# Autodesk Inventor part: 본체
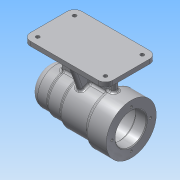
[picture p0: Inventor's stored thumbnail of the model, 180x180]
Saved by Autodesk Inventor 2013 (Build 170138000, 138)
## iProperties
Created: 2016-06
Part Number: 본체
Material: 알루미늄 6061
Document SubType Name: Modeling
Designer: Administrator
Density: 2.71 g/cm^3
Mass: 673.897 g
Surface Area: 647.23 cm^2
Volume: 248.671 cm^3
Author: Administrator
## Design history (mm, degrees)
sketch "스케치1"
  geometry: L1 (0, 0)-(0, 25); L2 (0, 25)-(25, 25); L3 (25, 25)-(25, 27); L4 (25, 27)-(45, 27); L5 (45, 27)-(45, 30); L6 (45, 30)-(84, 30); L7 (84, 30)-(84, 34); L8 (84, 34)-(112, 34); L9 (112, 34)-(112, 0); L10 (0, 0)-(112, 0)
  constraints: 20 end point, 6 perpendicular, 3 parallel, 1 vertical
  dimensions: "d0" = 25 distance of L1.start L1.end; "d1" = 25 distance of L1.end L2.end; "d2" = 2 distance of L2.end L3.end; "d3" = 20 distance of L3.end L4.end; "d4" = 3 distance of L4.end L5.end; "d5" = 39 distance of L5.end L6.end; "d6" = 4 distance of L6.end L7.end; "d7" = 28 distance of L7.end L8.end
revolve "회전1" sketch "스케치1" stored, may be unused: angle "d8" = 90 deg
sketch "스케치2"
  geometry: C1 r 34 at (0, 0) reference; C2 r 21 at (0, 0)
  constraints: 1 centre point, 1 coincident
  dimensions: "d9" = 42 diameter of C2
extrude "돌출1" cut sketch "스케치2" distance "d10" = 15; taper "d11" = 0 deg
sketch "스케치3"
  geometry: C1 r 21 at (0, 0) reference; C2 r 24 at (0, 0)
  constraints: 1 centre point, 1 coincident
  dimensions: "d12" = 48 diameter of C2
extrude "돌출2" cut sketch "스케치3" distance "d13" = 54; taper "d14" = 0 deg
sketch "스케치4"
  geometry: C1 r 24 at (0, 0) reference; C2 r 21 at (0, 0)
  constraints: 1 centre point, 1 coincident
  dimensions: "d15" = 42 diameter of C2
extrude "돌출3" cut sketch "스케치4" distance "d16" = 12; taper "d17" = 0 deg
sketch "스케치5"
  geometry: C1 r 21 at (0, 0) reference; C2 r 17.5 at (0, 0)
  constraints: 1 centre point, 1 coincident
  dimensions: "d18" = 35 diameter of C2
extrude "돌출4" cut sketch "스케치5" distance "d19" = 18; taper "d20" = 0 deg
sketch "스케치6"
  geometry: C1 r 17.5 at (0, 0) reference; C2 r 16 at (0, 0)
  constraints: 1 centre point, 1 coincident
  dimensions: "d21" = 32 diameter of C2
extrude "돌출5" cut sketch "스케치6" distance "d22" = 4; taper "d23" = 0 deg
sketch "스케치7"
  geometry: C1 r 16 at (0, 0) reference; C2 r 10.5 at (0, 0)
  constraints: 1 centre point, 1 coincident
  dimensions: "d24" = 21 diameter of C2
extrude "돌출6" cut sketch "스케치7" distance "d25" = 3; taper "d26" = 0 deg
fillet "모깎기1" dims "d27" = 3
sketch "스케치8"
  geometry: 1 further point
fillet "모깎기2" dims "d28" = 3
sketch "스케치9"
  geometry: 1 further point
fillet "모깎기3" dims "d29" = 0.3
sketch "스케치10"
  geometry: 1 further point
sketch "스케치11" dims "d30" = 52
  geometry: L1 (0, 0)-(0, 26); C1 r 34 at (0, 0) reference; 1 further point
  constraints: 2 coincident, 2 end point, 1 vertical, 1 vertical alignment, 2 other
hole "구멍1" sketch "스케치11" at (0, 26) diameter "d31" = 3.242; stored, may be unused: countersink angle "d35" = 90 deg, drill point angle "d37" = 118 deg; dims "d32" = 8, "d33" = 4, "d34" = 2, "d36" = 11
chamfer "모따기1" distance "d41" = 1; stored, may be unused: second distance "d42" = 2, angle "d43" = 45 deg
fillet "모깎기4" dims "d44" = 10
fillet "모깎기5" dims "d45" = 3
node "작업 평면1"
sketch "스케치12"
  geometry: L1 (0, 15)-(0, -15) reference; L2 (-112, 34)-(-112, -34) reference; L3 (0, 0)-(0, 35); L4 (0, 35)-(-112, 35); L5 (-112, 35)-(-112, -35); L6 (-112, -35)-(0, -35); L7 (0, -35)-(0, 0)
  constraints: 10 end point, 2 parallel, 2 perpendicular, 1 point on line
  dimensions: "d47" = 35 distance of L3.start L3.end; "d48" = 112 distance of L3.end L4.end; "d49" = 70 distance of L4.end L5.end
extrude "돌출7" join sketch "스케치12" distance "d50" = 10; taper "d51" = 0 deg
sketch "스케치13"
  geometry: L1 (0, 35)-(-112, 35) reference; L2 (-112, -35)-(0, -35) reference; L3 (-56, -35)-(-56, 35); L4 (-20, 4)-(-92, 4); L5 (-92, 4)-(-92, -4); L6 (-92, -4)-(-20, -4); L7 (-20, -4)-(-20, 4); L8 (-20, 4)-(-92, -4); L9 (-92, 4)-(-20, -4); 2 further points
  constraints: 14 end point, 5 midpoint, 2 parallel, 1 horizontal, 1 perpendicular
  dimensions: "d54" = 8 distance of L5.end L4.end; "d56" = 6.34019 deg angle of L1 L8
extrude "돌출8" join sketch "스케치13" stored distance "d57" = 10; taper "d58" = 0 deg
node "작업 평면2"
sketch "스케치14"
  geometry: L1 (-35, 70)-(-35, 60) reference; L2 (35, 60)-(-35, 60) reference; L3 (-35, 60)-(-28, 60); L4 (-28, 60)-(-16.9, 29.502); 2 further points
  constraints: 4 end point, 1 point on line, 2 other
  dimensions: "d60" = 7 distance of L1.end L3.end; "d61" = 110 deg angle of L3 L4
feature "리브1" sketch "스케치14" dims "d62" = 1, "d63" = 8, "d64" = 0, "d65" = 0, "d66" = 1, "d67" = 1
fillet "모깎기6" dims "d68" = 3
fillet "모깎기7" dims "d69" = 10
sketch "스케치15"
  geometry: C1 r 4.5 at (-102, -25); C2 r 4.5 at (-102, 25); A1 r 10 centre (-102, -25) between (-112, -25) and (-102, -35) reference; A2 r 10 centre (-102, 25) between (-102, 35) and (-112, 25) reference; 1 further point
  constraints: 2 centre point, 2 coincident
  dimensions: "d70" = 9 diameter of C1; "d71" = 9 diameter of C2
extrude "돌출9" cut sketch "스케치15" distance "d72" = 4; taper "d73" = 0 deg
sketch "스케치16"
  geometry: C1 r 4.5 at (0, 0) reference; C2 r 2.5 at (0, 0); 1 further point
  constraints: 1 centre point, 1 coincident
  dimensions: "d74" = 5 diameter of C2
extrude "돌출10" cut sketch "스케치16" stored distance "d75" = 4; taper "d76" = 0 deg
sketch "스케치17"
  geometry: C1 r 4.5 at (0, 0) reference; C2 r 2.5 at (0, 0); 1 further point
  constraints: 1 centre point, 1 coincident
  dimensions: "d77" = 5 diameter of C2
extrude "돌출11" cut sketch "스케치17" stored distance "d78" = 4; taper "d79" = 0 deg
node "작업 평면3"
chamfer "모따기2" distance "d81" = 4; stored, may be unused: second distance "d82" = 2, angle "d83" = 45 deg
fillet "모깎기8" dims "d84" = 3
node "작업 평면4"
sketch "스케치18"
  geometry: L1 (17.304, -30)-(17.304, 29.317) reference; L2 (54.5, 70)-(-37.5, 70) reference; L3 (-47.5, 34)-(-47.5, -34) reference; 2 further points
  constraints: 1 other
  dimensions: "d85" = 70 distance from line of point (0.5, 0) L2; "d86" = 48 distance from line of point (0.5, 0) L3
feature "엠보싱1" sketch "스케치18" dims "d0" = 25, "d1" = 25, "d2" = 2, "d3" = 20, "d4" = 3, "d5" = 39, "d6" = 4, "d7" = 28, "d87" = 0.5, "d88" = 0
node "솔리드1"
pattern_circular "원형 패턴1" dims angle "d39" = 360 deg
mirror "대칭1"
mirror "대칭2"
other parameters: "d59" = 56, "d80" = 56
